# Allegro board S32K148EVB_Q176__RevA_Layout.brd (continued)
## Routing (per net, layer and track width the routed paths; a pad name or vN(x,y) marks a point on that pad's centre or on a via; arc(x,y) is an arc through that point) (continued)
P3V3_ENET: length 13.7
  TOP w0.279: J16.1 118.29,62.05 118.88,61.45 C549.1 119.49,62.04 119.21,62.04 118.71,62.55 J16.3
  TOP w0.635: R133.2 121.41,58.32 TPAD28.1 ; R133.2 C550.1 C549.1 ; R133.2 119.38,58.32 119.27,58.21 L4.2
P3V3_ENETSW: length 34.1
  TOP w0.203: U3.8 100.78,54.89 100.62,55.05 v1(99.58,55.05) ; R185.1 94.92,52.03 94.34,51.45 U10.8 ; R201.1 99.28,47.29 99.98,46.58 U12.8
  TOP w0.508: R202.1 v1(104.84,48.09) ; R201.1 98.79,48.09 98.29,47.58 v1(98.29,47.25) ; R199.1 v1(96.79,47.71) ; R144.1 TPAD31.1
  TOP w0.635: C17.1 C18.1 C19.1 101.43,58.18 101.31,58.05 R142.1 ; R142.1 R144.1 ; R142.1 100.42,57.36 v1(100.06,57.72) ; v1(97.55,50.51) 97.27,50.79 97.27,51.5 96.74,52.03 R185.1
  BOTTOM w0.203: v1(97.55,50.51) 97.78,50.28 99.15,50.28 99.38,50.51 U505.8
  BOTTOM w0.635: R521.1 99.81,60.2 R522.1 99.83,58.65 100.06,58.42 v1(100.06,57.72) ; R556.1 103.85,49.08 v1(104.84,48.09) ; R551.1 v1(104.76,51.22)
P3V3_SDA: length 59
  TOP w0.229: R301.1 14.06,12.46 R308.1
  TOP w0.279: R308.1 v1(13.04,13.37)
  TOP w0.508: v1(19.37,21.19) 19.8,20.76 U23.5 C97.1 ; v1(17.08,20.81) 17.54,21.27 R285.2 ; R281.1 v1(13.77,22.95) ; R291.1 9.6,19.57 R288.1 10.95,19.58 11.32,19.95 12.79,19.95 12.8,19.96 v1(13.64,19.96) ; R286.1 v1(25.79,20.97)
  TOP w0.635: v1(33.19,20.46) 33.74,21.02 TP55.1 34.89,21.19 TPAD48.1
  L4_PWR_1 w0.508: 21.6,27.89 J20.1 22.33,26.55
  BOTTOM w0.203: U509.1 v1(35.14,16.62)
  BOTTOM w0.279: 30.67,14.65 30.58,14.74 R622.1 ; 30.67,14.65 U511.1 ; 30.67,14.65 v1(30.63,14.65) ; U510.1 14.44,15.15 13.98,14.69 v1(13.98,14.59) 13.96,14.62 C545.1 ; v1(17.08,20.81) 16.68,20.41 16.68,20.02 16.74,19.96 U510.11 ; v1(13.64,19.96) 13.64,19.44 14.01,19.07 14.01,18.61 14.47,18.15 U510.7 ; v1(17.87,8.09) R631.1 ; U513.7 21.43,13.72 21.15,14.01 v1(21.15,14.21)
  BOTTOM w0.305: C535.1 16.03,22.26 16.52,21.77 16.52,21.38 v1(17.08,20.81) ; U514.1 16.96,12.24 16.73,12 16.73,10.48 16.95,10.26 16.95,9.11 17.49,8.57 17.49,8.46 v1(17.87,8.09) ; U512.1 26.64,15.06 26.4,15.3 25.78,15.3 v1(25.78,15.3) 25.44,15.63 R621.1
  BOTTOM w0.406: v1(13.04,13.37) C545.1 ; R605.1 21.73,26.68
  BOTTOM w0.508: R607.1 v1(13.5,26.32) ; 21.73,26.68 J20.1 ; C538.1 C536.1 13.14,20.46 v1(13.64,19.96) ; C540.1 C539.1 R613.1 32.22,16.85 32.68,16.39 R616.1 34.28,16.39 34.51,16.62 v1(35.14,16.62)
  BOTTOM w0.635: R610.1 v1(33.19,20.46) ; C533.1 R606.1 23.33,26.38 23.15,26.55 J20.1
P3V3_SW: length 308.3
  TOP w0.508: TPAD50.1 83.25,15.2 C104.1 ; v1(84.8,17.64) C99.1
  TOP w0.635: R41.1 v1(122.9,74) 123.46,74 123.91,73.55 123.91,58.4 122.22,56.72 R133.1 119.35,56.72 119.24,56.83 L4.1 118.58,56.83 TS7.1 v1(113.5,56.83) ; C85.1 34.89,31.84 TP53.1 J3.10 ; P1.1 83.53,10.75 84.54,11.77 C104.1 84.54,16.47 C99.1 ; R182.2 50.19,52.35 TP26.1 52.65,52.91 R633.2 52.65,55.4 TPAD35.1 ; R288.2 v1(8.69,21.18)
  L4_PWR_1 w0.635: v1(84.8,17.64) 85.5,17.64 85.74,17.4 105.56,17.4 106.03,17.87 106.03,43.23 106.77,43.96 106.77,47.38 113.31,53.92 113.31,54.1 113.68,54.47 113.68,56.65 v1(113.5,56.83) 111.62,56.83 106.64,61.81 101.28,61.81 98.5,64.59 98.14,64.59 v1(97.65,65.09) ; J7.1 36.78,70.66 37.34,70.66 37.74,70.25 37.74,65.21 38.38,64.58 40.37,64.58 41.01,63.94 41.01,62.85 42.18,61.68 42.18,56.78 47.56,51.39 TP26.1
  L5_PWR_2 w0.508: J3.10 36.54,29.17 ; J3.10 35.52,30.19 ; J3.10 35.52,28.15 ; J3.10 34.51,29.17
  L5_PWR_2 w0.635: J7.1 36.93,73.02 44.42,73.02 45.22,72.22 50.74,72.22 53.02,74.51 57.82,74.51 57.99,74.34 71.63,74.34 73.53,72.44 81.25,72.44 82.7,73.89 91.92,73.89 96.24,69.57 96.24,64.36 96.65,63.95 97.23,63.95 97.65,64.38 v1(97.65,65.09)
  L6_INT_2 w0.508: v1(103.42,79.66) 108.06,79.66 109.56,81.16 115.74,81.16 v1(122.9,74)
  L6_INT_2 w0.635: J7.1 34.38,73.06 30.98,73.06 30.06,72.15 20.64,72.15 19.24,73.54 17.82,73.54 17.44,73.92 13.68,73.92 12.66,74.94 7.66,74.94 v1(6.01,76.59)
  BOTTOM w0.508: R574.2 L500.2 39.46,39.3 38.98,38.82 38.98,37.98 v1(38.15,37.16) ; R501.2 v1(103.42,79.66) ; v1(97.65,65.09) 97.65,64.45 98.41,63.69 R521.2
  BOTTOM w0.635: R504.2 v1(6.01,76.59)
P5V0: length 310.9
  TOP w0.635: C113.1 C112.1 22.57,13.14 TPAD51.1 ; C113.1 23.69,10.75 v1(24.04,11.11) ; C113.1 P1.49 ; TS12.1 104.41,40.83 v1(104.05,41.18) ; v1(14.17,74.85) R12.1 R9.1 ; C79.1 TP52.1 J3.13 ; TPAD2.1 v1(122.9,75.78) ; v1(46.9,55.59) 46.9,53.68 47.21,53.38 R181.2
  TOP w0.762: J18.3 J7.3 37,68.01 37.81,68.01 J8.2 ; R35.1 R6.1 TPAD2.1 ; D6.A1 D6.A2 ; D6.A2 D6.A3 ; D6.A2 102.91,38.31 103.01,38.42 TS12.1
  L4_PWR_1 w0.635: J18.3 34.29,68.6 34.29,72.9 33.54,73.65 31.08,73.65 30.11,72.68 20.49,72.68 19.48,73.68 15.34,73.68 v1(14.17,74.85) ; v1(46.9,55.59) 45.71,55.59 44.95,56.35 44.95,65.11 43.09,66.96 41.29,66.96 J8.2 45.3,69.23 45.42,69.34 54.03,69.34 57.53,65.83 81.51,65.83 83.26,67.59 97.79,67.59 v1(99.38,66) 99.38,72.5 100.95,74.08 121.2,74.08 v1(122.9,75.78)
  L5_PWR_2 w0.635: v1(104.05,41.18) 104.05,45.53 106.64,48.12 106.64,58.15 102.45,62.34 102.45,62.93 v1(99.38,66) ; v1(24.04,11.11) 25.49,9.66 27.27,9.66 28.77,11.16 30.87,11.16 32.04,9.99 44.59,9.99 48.04,13.45 48.04,29.7 46.67,31.07 39.97,31.07 J3.13 38.06,32.43 39.98,34.35 45.6,34.35 47.28,36.03 47.28,38.57 49.14,40.42 49.14,45.86 52.79,49.52 52.79,52.08 49.29,55.59 v1(46.9,55.59)
  BOTTOM w0.635: v1(99.38,66) 99.83,65.54 R522.2
P5V0_SDA_USB_CONN_VBUS: length 8.4
  TOP w0.279: v1(8.12,10.45) 8.41,10.74 L9.1
  TOP w0.406: J24.1 5.2,11.87 6.62,10.45 v1(8.12,10.45)
  BOTTOM w0.279: v1(8.12,10.45) 8.85,10.45 9.13,10.73 9.13,11.36 8.93,11.57 U515.5
P5V0_V1SBC: length 106.2
  TOP w0.279: 27.83,58.25 27.55,58.53 v1(27.55,58.61)
  TOP w0.356: U9.6 27.57,51.45 27.88,51.14
  TOP w0.406: R140.1 27.83,58.25
  TOP w0.508: R132.1 25.74,61.1 25.77,61.12 25.77,61.16 v1(25.77,61.16) ; v1(30.31,52.39) 30.31,52.31 30.19,52.18 TS10.1
  TOP w0.635: C31.1 31.85,52.8 31.85,52.47 32.02,52.31 C45.1 C47.1 30.7,49.62 TS10.1 28.85,50.12 27.88,51.1 27.88,51.14 ; 39.03,73.06 39.03,73.62 TPAD7.1
  TOP w0.762: 39.03,73.06 J8.1
  L3_INT_1 w0.508: v1(27.55,58.61) 28,59.07 30.2,59.07 31.66,57.6 31.66,55.89 30.42,54.65 30.42,53.12 30.31,53.02 v1(30.31,52.39)
  L5_PWR_2 w0.635: v1(27.55,58.61) 25.77,60.38 v1(25.77,61.16) 26.26,61.65 26.26,63.17 20.23,69.2 17.28,69.2 TP5.1 16.29,73.59 19.72,73.59 21.45,71.87 28.82,71.87 29.97,73.02 32.89,73.02 33.67,72.25 33.67,71.99 35.17,70.5 37.76,70.5 J8.1
  BOTTOM w0.406: v1(27.55,58.61) 27.32,58.38 R531.1
  BOTTOM w0.508: R517.2 22.34,64.51 22.95,65.12 22.95,66.74 20.76,68.92 17.56,68.92 TP5.1 14.59,67.07 17.72,63.94 17.72,59.8 18.45,59.07 R526.1
P5V0_V2SBC: length 30.7
  TOP w0.279: U9.3 27.64,49.5 27.83,49.31
  TOP w0.406: 27.83,49.31 28.49,48.65 28.49,48.32 R204.1 29.63,47.61 29.98,47.25 30.49,47.25 v1(30.77,46.98)
  L5_PWR_2 w0.635: v1(30.77,46.98) 30.87,46.87 30.87,41.92 22.95,34 JP1.1
  BOTTOM w0.508: JP1.1 21.68,31.76 21.65,31.79 J15.1
  BOTTOM w0.635: C528.1 C526.1 31.18,46.57 v1(30.77,46.98)
P5V_SDA: length 13
  TOP w0.279: R293.1 7.33,16.9 v1(7.84,17.41) 8.93,17.41 9.36,16.98 9.36,16.29 9.58,16.07 U24.1
  TOP w0.406: C89.1 14.57,18.04 14.26,17.74 14.09,17.74 ; v1(14.09,17.79) 14.09,17.74 ; 14.09,17.74 14.82,17.01 C103.1
  TOP w0.508: v1(9.17,12.86) 9.81,12.23 L9.2
  TOP w0.635: C111.1 v1(9.17,12.86)
  BOTTOM w0.279: R615.1 v1(25.31,17.66) ; U510.6 14.23,17.65 v1(14.09,17.79) ; v1(14.72,9.54) 15.24,9.54 15.51,9.81 R628.1
P5V_SDA_PSW: length 86.2
  TOP w0.508: TPAD49.1 12.9,17.51 U24.6
  TOP w0.635: TPAD49.1 12.38,17.51 11.95,17.08 v1(10.4,17.08)
  L5_PWR_2 w0.635: v1(7.05,29.47) 7.05,50.3 7.67,50.92 7.67,55.42 8.65,56.4 14.01,56.4 16.34,54.06 19.75,54.06 22.67,56.98 24.45,56.98 25.41,56.02 26.63,56.02 28.89,58.28 28.89,61.37 28.4,61.86 28.4,62.84 30.24,64.68 37.02,64.68 J8.3
  BOTTOM w0.635: v1(10.4,17.08) 7.05,20.43 v1(7.05,29.47)
VBAT: length 56.8
  TOP w0.635: J3.22 C86.1 ; TP2.1 J18.1 ; 16.32,65.39 C12.1 ; C12.1 16.83,65.9 ; C12.1 15.81,65.9 ; J3.1 C82.1
  TOP w0.889: R180.2 9.08,51.32 9.91,52.14 v1(10.25,52.14) R163.1 ; R180.2 v1(6.97,51.32) ; R180.2 v1(8.22,50.44) ; D4.A 17.6,63.08 ; D4.A 18.49,64.32 ; D4.A 16.71,64.32 ; D4.A 17.6,65.57 ; J9.1 12.29,63.97 ; J9.1 8.46,63.97 ; J9.1 10.38,64.88
  TOP w1.016: J3.3 J3.6
  L4_PWR_1 w0.508: 26.89,29.17 J3.1 ; J3.1 27.9,28.15 ; J3.1 28.92,29.17 ; J3.1 27.9,30.19 ; 26.89,24.09 J3.3 ; J3.3 28.92,24.09 ; J3.3 27.9,25.11 ; J3.6 31.46,24.09 ; J3.6 30.44,25.11 ; J3.6 29.43,24.09 ; 8.46,63.97 J9.1 ; J9.1 10.38,63.05 ; J9.1 10.38,64.88 ; J9.1 12.29,63.97 ; 2.63,28.15 J17.2 ; J17.2 3.64,29.17 ; J17.2 3.64,27.14 ; J17.2 4.66,28.15 ; J3.22 45.68,30.19 ; J3.22 45.68,28.15 ; J3.22 44.67,29.17 ; J18.1 33.33,71.77 ; J18.1 31.42,71.77 ; J18.1 32.37,70.81 ; J18.1 32.37,72.72 ; 3.64,41.23 J13.2 ; J13.2 4.66,42.25 ; J13.2 3.64,43.27 ; J13.2 2.63,42.25
  vias: v1(19.01,66.23) v1(19.01,65.54)
VCC_HYPRFLASH: length 23.9
  L6_INT_2 w0.191: v1(34.79,41.59) 34.28,41.59 33.94,41.93 v1(32.83,43.04)
  BOTTOM w0.279: R574.1 R575.1
  BOTTOM w0.406: v1(34.79,41.59) 35.52,41.59 35.93,42 TPAD504.1 37.13,41.98 R575.1 ; v1(32.83,43.04) 31.41,43.04 29.12,40.75 26.37,40.75 25.12,42 C529.1 C531.1 C532.1 U508.8 ; L500.1 R574.1
VCCA_LS_SBC: length 90.1
  TOP w0.508: R153.1 34.89,55.63 35.15,55.89 35.83,55.89 v1(36.23,56.29)
  L3_INT_1 w0.635: v1(30.31,47.92) 30.8,48.41 30.81,48.41 v1(35.24,52.84) ; v1(23.28,63.97) 21.24,63.97 19.72,62.44 v1(18.96,62.44) 17.98,62.44 13.7,58.16 v1(13.7,57.47)
  L6_INT_2 w0.635: v1(30.31,47.92) 29.81,47.42 23.76,47.42 22.8,48.39 22.8,50.58 23.66,51.45 v1(23.66,52.66) 21.81,54.52 15.79,54.52 13.7,56.6 v1(13.7,57.47) ; v1(29.93,58.43) 29.11,57.6 29.11,55.7 31.97,52.84 v1(35.24,52.84)
  BOTTOM w0.203: U507.1 27.71,49.07 28.87,47.92 v1(30.31,47.92) ; v1(13.7,57.47) 13.7,58.1 14.47,58.86 U502.1 ; v1(36.23,56.29) 36.23,56.91 35.37,57.77 U503.1 ; U500.1 v1(23.28,63.97) ; 22.87,54.72 22.29,54.72 22.14,54.87 U504.1 ; U506.1 35.07,52.13 35.24,52.31 v1(35.24,52.84) ; v1(29.93,58.43) 29.93,58.91 30.1,59.08 30.1,59.39 29.83,59.65 U501.1
  BOTTOM w0.406: v1(35.24,52.84) 35.24,53.43 35.22,53.45 35.22,54.09 36.23,55.1 v1(36.23,56.29)
  BOTTOM w0.508: 26.61,53.88 C521.1 TP505.1 ; v1(23.66,52.66) 24.3,52.66 24.35,52.72 TP505.1 ; C520.1 22.97,54.62 22.87,54.72 ; TP505.1 26.61,52.06 26.1,51.55 R550.2 ; v1(18.96,62.44) 21.57,59.84 21.57,59.33 R525.2
  BOTTOM w0.635: v1(23.66,52.66) 23.66,53.27 C522.1 C520.1 ; C519.1 26.61,53.88
VCCA_VTRANSL: length 117.6
  TOP w0.279: C80.1 50.89,33.82 51.03,33.96 U16.14 ; C46.1 35.32,49.41 35.51,49.22 35.51,49.2 v1(35.88,48.83) 36.6,48.83 36.84,49.07 U11.14 ; C68.1 37.38,39.33 37.39,39.32 U14.14 ; U22.14 62.58,32.81 62.57,32.8 C83.1 ; U13.14 46.77,43.19 47.03,42.94 v1(47.56,42.94)
  TOP w0.406: C61.1 47.89,43.27 v1(47.56,42.94)
  TOP w0.508: C68.1 35.45,39.33 v1(35.14,39.63) ; C80.1 48.65,33.11 v1(47.38,34.38) 47.38,32.42 49.06,30.74 49.06,28.27 49.43,27.9 58.89,27.9 59.66,28.67 59.66,29.69 60.41,30.44 62.09,30.44 v1(62.57,30.92) C83.1
  TOP w0.635: TS8.1 40.65,52.54 39.76,53.43 R176.1 v1(39.2,54.7) ; C59.1 C61.1 TPAD40.1 48.6,41.49 L7.2 R242.2
  L3_INT_1 w0.508: v1(62.57,30.92) 63.28,31.63 v1(63.28,33.54) ; v1(35.88,48.83) 35.88,47.89 35.57,47.58 35.57,45.59 36.9,44.26 36.93,44.26 37.45,43.73 37.45,42.78 35.14,40.46 v1(35.14,39.63)
  BOTTOM w0.406: v1(47.38,34.38) 47.74,34.02 49.49,34.02 50.46,34.99 50.46,38.82 48.65,40.63 C530.1 48.65,42.66 48.37,42.94 v1(47.56,42.94) 47.56,43.52 47.31,43.77 C527.1
  BOTTOM w0.508: R548.1 R547.1 R546.1 38.19,54.24 38.65,54.7 v1(39.2,54.7) 39.2,53.81 39.56,53.45 39.56,51.17 37.22,48.83 v1(35.88,48.83) 35.88,45.58 R572.1 R571.1 R570.1 40.75,43.14 42.66,41.23 R573.1 42.66,40.4 43.19,39.86 R579.1 R578.1 R577.1 R576.1 47.08,39.43 R582.1 R584.1 R588.1 R593.1 47.08,34.68 v1(47.38,34.38)
  BOTTOM w0.635: v1(63.28,33.54) R603.1 R597.1 R594.1 R589.1
VCCB_VTRANSL: length 129.3
  TOP w0.279: U14.1 37.39,37.82 37.38,37.81 C75.1 ; C55.1 35.85,47.99 36.54,47.31 v1(36.84,47.31) U11.1 ; C84.1 64.1,32.8 64.08,32.81 U22.1 ; C81.1 52.41,33.82 52.53,33.93 U16.1 ; R214.1 v1(42.3,44.28) ; C56.1 48.12,46.31 47.79,45.98 47.79,45.6 47.47,45.29 U13.1
  TOP w0.406: C75.1 35.65,37.81 v1(35.27,38.19) ; v1(48.98,48.91) 48.98,49.49 48.58,49.9 R182.1 R181.1 46.15,50.75 45.81,51.09 C41.1 C32.1
  TOP w0.508: R273.1 68.54,32.75 66.46,30.66 64.46,30.66 64.1,31.02 C84.1
  TOP w0.635: C81.1 53.1,33.11 53.61,33.61 TPAD45.1 55.07,32.87 v1(55.07,32.87) ; C32.1 v1(44.34,51.14) ; R252.1 R258.1 R263.1 R273.1 v1(70,33.74) TS14.1 ; C56.1 C53.1 v1(48.98,48.91)
  L3_INT_1 w0.508: v1(42.3,44.28) 44.01,45.98 44.01,48.75 43.75,49.01 43.75,50.58 44.31,51.14 v1(44.34,51.14) ; v1(43.24,32.56) 42.6,31.92 38.22,31.92 36.23,33.91 36.23,37.22 v1(35.27,38.19) 37.02,39.94 37.02,41.45 38.09,42.51 38.09,44 37.19,44.89 37.16,44.89 36.21,45.85 36.21,46.67 v1(36.84,47.31)
  L6_INT_2 w0.508: v1(55.07,32.87) 51.03,32.87 50.63,32.47 46.44,32.47 46.36,32.56 v1(43.24,32.56)
  BOTTOM w0.406: v1(44.34,51.14) 44.31,51.14 43.88,50.71 R553.2 43.37,50.66 R559.1 ; v1(43.24,32.56) R599.1
  BOTTOM w0.508: v1(55.07,32.87) 56.28,31.66 60.77,31.66 61.18,32.07 66.23,32.07 67.91,33.74 v1(70,33.74) ; v1(36.84,47.31) 37.34,47.8 38.48,47.8 38.98,47.31 R566.1 40.2,47.03 42.3,44.92 v1(42.3,44.28) R568.1 R569.1
  BOTTOM w0.635: R599.1 42.15,33.31 42.1,33.36 41.26,33.36 R600.1 R601.1 R602.1 ; R557.1 R558.1 R559.1 R560.1 ; R587.1 R592.1 R596.1 56.6,34.02 55.95,33.36 55.56,33.36 v1(55.07,32.87) 54.25,32.87 R598.1
VDD: length 188.9
  TOP w0.635: TPAD12.1 59.78,70.06 R59.1 ; TS15.1 40.22,14.54 39.67,13.99 v1(38.28,13.99) R299.2 ; R59.1 R60.1 ; R59.1 57.84,71.3 J19.2
  L4_PWR_1 w0.635: J19.2 56,71.17 52.35,71.17 51.47,72.04 47.84,72.04 46.55,73.34 37.3,73.34 35.98,74.66 30.62,74.66 29.83,73.87 28.13,73.87 26.52,75.49 18.67,75.49 16.57,77.58 13.74,77.58 13.11,76.94 13.11,75.66 v1(13.22,75.55)
  L5_PWR_2 w0.635: v1(38.28,13.99) 35.15,13.99 29.5,19.64 21.25,19.64 20.64,19.04 16.24,19.04 14.57,20.71 11.11,20.71 9.89,19.49 4.99,19.49 2.3,22.18 2.3,59.07 2.93,59.7 4.74,59.7 6.85,61.81 6.85,72.65 9.74,75.55 v1(13.22,75.55) ; J7.2 36.96,67.94 40.31,67.94 40.59,67.66 54.2,67.66 J19.2
  BOTTOM w0.635: v1(13.22,75.55) 13.22,75.47 13.14,75.47 12.84,75.17 TPAD502.1 R505.2
VDD_MCU: length 71.4
  TOP w0.203: U8.39 60.29,67.4 60.29,67.4 60.29,67.78 60.29,67.79 v1(60.29,68.04) ; v1(59.93,47.43) 59.2,47.43 59.2,47.42 58.82,47.42 58.81,47.43 U7.67 ; U8.77 v1(54.18,48.43) ; U7.11 72.29,63.42 72.28,63.41 72.28,63.01 72.28,63 72.28,62.78 v1(72.29,62.77) ; U8.59 v1(54.17,57.43) ; 83.93,52.03 83.72,52.03 83.22,52.52 82.48,52.52 82.44,52.48 ; 77.8,40.98 v1(77.8,39.32) ; U7.51 58.81,55.43 58.81,55.44 59.2,55.44 59.2,55.43 v1(59.92,55.43) ; 68.29,40.98 v1(68.29,39.32)
  TOP w0.254: U7.91 v1(68.79,44.12) ; U8.152 82.2,52.43 82.22,52.48 82.44,52.48 ; U7.124 77.64,52.43 v1(77.11,52.96) ; U8.18 v1(70.79,67.57) ; U8.172 v1(82.44,62.44) ; U7.32 v1(61.79,63.24)
  TOP w0.279: U7.124 81.24,52.43 U8.152
  TOP w0.508: C9.1 60.29,68.94 v1(60.29,68.04) ; C50.1 53.97,48.22 v1(54.18,48.43) ; v1(54.17,57.43) 53.78,57.43 53.58,57.24 C23.1 ; C72.1 77.8,38.45 v1(77.8,39.32) ; C73.1 68.54,39.07 v1(68.29,39.32) ; C44.1 83.93,52.03
  TOP w0.635: R59.2 58.1,72.9 58.06,72.86 J19.1 ; TPAD44.1 77.89,38.26 C72.1 ; D2.1 83.27,68.29 82.87,67.88 v1(81.29,67.88) ; D2.1 82.19,69.43 82.07,69.3 L1.1 ; D2.1 84.35,69.43 84.94,70.01 84.94,70.95 85.57,71.59 TS4.1 ; TPAD32.1 C23.1
  L5_PWR_2 w0.508: 55.9,72.86 J19.1 ; J19.1 56.86,73.81 ; J19.1 56.86,71.9 ; J19.1 57.81,72.86
  BOTTOM w0.203: C503.1 83.27,62.62 83.11,62.46 82.94,62.46 82.92,62.44 v1(82.44,62.44) ; 71.03,68.77 70.79,68.53 v1(70.79,67.57) ; v1(61.79,63.24) 61.79,62.76 61.81,62.74 61.81,62.57 61.81,62.57 C505.1 ; v1(72.29,62.77) 72.78,62.28 73.02,62.28 73.49,61.81 C510.1
  BOTTOM w0.508: v1(68.79,44.12) 68.66,44.26 68.66,44.86 68.8,45 C525.1 ; C518.1 60.08,55.33 59.98,55.43 v1(59.92,55.43) ; C504.1 74.76,61.81 C510.1 ; v1(77.11,52.96) 76.9,52.74 C524.1 ; C502.1 71.03,69.28 71.03,68.77
  BOTTOM w0.635: C516.1 60.67,56.25 60.79,56.12 C518.1 ; v1(81.29,67.88) 81.29,68.72 80.71,69.3 R509.2
VDD_MCU_ENETSW: length 35.4
  TOP w0.203: R178.1 93.18,51.67 93.69,51.17 U10.1 ; U12.1 99.31,45.93 99.19,46.06 R207.1 ; U3.1 99.44,53.81 99.19,53.55 L6.2
  TOP w0.508: v1(93.97,46.11) 92.62,47.46 R200.1 ; R207.1 97.57,46.06 v1(97.19,46.44) ; R188.1 v1(104.66,50.38) ; R190.1 98.22,49.87 97.89,49.54 97.68,49.54 v1(97.57,49.44) ; R156.1 v1(105.74,53.81) ; R217.1 v1(105.37,44.52)
  TOP w0.635: R179.2 L6.2 98.64,54.7 C28.1 C27.1 95.72,54.95 TPAD36.1 93.81,54.19 v1(93.18,53.55) R178.1
  BOTTOM w0.203: v1(98.13,51.19) 98.13,52.11 98.39,52.36 U505.1
  BOTTOM w0.508: v1(104.72,55.11) 103.56,56.27 R539.1 ; v1(94.17,55.29) 94.68,54.78 95.4,54.78 95.57,54.95 C27.1 95.92,54.14 R545.1
VDD_MCU_PERH: length 159.4
  TOP w0.406: 87.46,67.65 85.38,67.65 85.26,67.52 TPAD17.1 ; R121.1 R113.1
  TOP w0.508: TP6.1 v1(97.07,70.06) 96.94,69.94 R72.1 ; J5.10 C88.1 ; R36.1 21.04,74.31 v1(21.58,73.77) ; R107.1 R95.1 R90.1 v1(97.27,66.89) ; J6.14 82.51,78.7 82.51,76.03 C2.1 84.04,73.95 84.59,73.39 v1(84.59,72.98) ; R37.1 v1(24.09,73.89) ; v1(95.03,52.94) 95.64,53.55 L6.1 ; v1(83.67,62) 84.16,61.5 R113.1 ; R60.2 v1(63.12,72.9) ; R242.1 49.62,38.8 49.77,38.64 49.77,38.64 v1(49.81,38.64) ; R161.2 v1(114.01,53.81)
  TOP w0.635: SW4.3 SW4.1 v1(97.16,11.38) ; SW3.3 SW3.1 90.59,9.81 v1(90.59,11.59) 89.8,12.38 TS16.1 ; R179.1 L6.1 ; C88.1 83.78,23.51 v1(83.32,23.05) ; L7.1 R242.1 ; J3.4 30.54,29.27 C87.1 ; C551.1 84.54,66.99 TPAD17.1 84.54,68.35 85.7,69.51 85.7,70.13 v1(86.19,70.62)
  L3_INT_1 w0.762: v1(24.09,73.89) 24.63,73.35 24.69,73.35 28.59,69.45 28.59,68.29 32.47,64.4 42.04,64.4 42.45,64.81 43.08,64.81 43.14,64.74 v1(43.71,64.74)
  L4_PWR_1 w0.508: v1(21.58,73.77) 22.16,74.36 23.3,74.36 23.33,74.34 23.64,74.34 v1(24.09,73.89) ; 83.78,25.6 J5.10 ; J5.10 83.78,27.66 ; J5.10 82.75,26.63 ; J5.10 84.81,26.63
  L5_PWR_2 w0.762: J3.4 28.92,30.69 25.46,30.69 24.73,29.96 22.03,29.96 21.42,30.57 21.42,32.01 19.77,33.67 19.77,36.48 23.23,39.94 23.23,47.08 v1(22.06,48.25) 22.06,49.27 25.94,53.15 32.41,53.15 32.85,53.59 32.85,53.99 34.38,55.51 34.38,59.6 39.52,64.74 v1(43.71,64.74)
  BOTTOM w0.508: R518.1 96.15,60.74 v1(97.14,59.75) ; R550.1 23.94,51.55 22.06,49.67 v1(22.06,48.25)
VDDA_MCU: length 33.5
  TOP w0.16: U7.13 v1(71.29,62.62) ; v1(69.78,67.63) 69.79,67.63 U8.20
  TOP w0.203: 69.78,68.7 69.78,68.44 69.79,68.43 69.79,68.12 69.78,68.11 v1(69.78,67.63)
  TOP w0.508: L1.2 79.26,69.3 v1(78.36,70.2) 77.7,70.2 TPAD14.1 76.03,69.3 75.91,69.43 D1.1 C5.1 72.86,69.3 C7.1 C6.1 69.78,68.76 69.78,68.7
  TOP w0.635: L1.2 80.1,70.71 79.44,71.37 TS3.1
  BOTTOM w0.191: 71.29,63.81 71.29,63.45 71.3,63.43 71.3,63.11 71.29,63.1 v1(71.29,62.62)
  BOTTOM w0.203: 70.07,68.79 69.78,68.51 69.78,68.44 69.79,68.43 69.79,68.12 69.78,68.11 v1(69.78,67.63)
  BOTTOM w0.381: 70,66.67 69.78,66.9 v1(69.78,67.63)
  BOTTOM w0.508: 70,66.67 71.29,65.38 71.29,63.81 ; R509.1 v1(78.36,70.2) ; C506.1 70.83,62.16 v1(71.29,62.62) ; 70.07,68.79 70.07,69.14 70.09,69.16 R508.2
  BOTTOM w0.635: C509.1 C508.1 C507.1 C506.1 C511.1
ADC_POT: length 83
  TOP w0.406: v1(110.48,49.36) C48.1 R194.2 TP27.1
  L3_INT_1 w0.191: v1(93.99,52.03) 93.99,47.62 94.46,47.16 94.68,47.16 96.38,45.46 106.57,45.46 v1(110.48,49.36)
  L6_INT_2 w0.191: v1(93.99,52.03) 92.37,52.03 90.82,50.48 90.82,48.6 89.52,47.31 89.52,43.77 85.24,39.48 84.09,39.48 84.08,39.49 83.93,39.49 ; v1(65.26,38.11) 69.05,38.11 70.85,36.31 73.98,36.31 75.93,38.26 81.93,38.26 82.28,38.62
  L6_INT_2 w0.203: 82.28,38.62 83.15,39.48 83.2,39.48 83.21,39.49 83.93,39.49
  BOTTOM w0.203: 67.27,38.62 67.81,39.15 67.81,39.56 68.08,39.84 68.08,44.94 67.5,45.53 67.5,46.47 68.77,47.74 69.62,47.74 70.27,47.09 R634.1
  BOTTOM w0.406: 67.27,38.62 66.77,38.11 v1(65.26,38.11) 64.68,38.11 64.45,38.34 R583.1
CAN_H: length 18.8
  TOP w0.254: J11.1 4.6,57.43 6.64,57.43 6.93,57.72 C20.1 7.87,57.72 8.17,57.43 8.82,57.43 8.89,57.5 9.46,57.5 9.77,57.56 9.97,57.86 R125.1 11.65,58.38 12.08,57.94 12.57,57.94 12.9,58.27 12.9,58.31 12.94,58.35 ; 13.65,59.07 13.65,61.17 14.34,61.86 TP11.1
  TOP w0.279: 13.65,59.07 12.94,58.35
  TOP w0.406: R112.2 TP11.1
CAN_L: length 14.4
  TOP w0.254: 13.25,58.05 13.2,58 13.17,58 12.72,57.56 12.55,57.56 12.31,57.31 12.31,57.26 12.28,57.24 R138.2 TP20.1 10.15,56.99 9.85,57.19 9.49,57.12 9.05,57.12 8.98,57.05 8.17,57.05 7.87,56.75 C25.1 6.93,56.75 6.64,57.05 4.85,57.05 J11.2
  TOP w0.279: R135.2 14.03,58.84 13.25,58.05
CANH_OUT: length 74.6
  TOP w0.254: R119.2 15.91,60.84 15.44,60.37 15.29,60.37 14.82,60.84 v1(14.47,60.84)
  L6_INT_2 w0.191: v1(14.47,60.84) 13.99,60.58 13.69,60.67 12.32,60.67 11.4,59.76 11.4,54.88 11.4,54.62 16.37,49.65 16.8,49.65 17.45,49 17.45,42.86 27.81,32.49 27.81,31.15 29.01,29.95 29.01,22.64 29.56,22.08 v1(29.56,21.68)
  BOTTOM w0.254: v1(29.56,21.68) 29.56,22.08 29.12,22.51 27.98,22.51 27.65,22.18 27.65,21.37 28.28,20.74 29.76,20.74 30.92,21.91 33.82,21.91 34.28,22.36 41.52,22.36 41.9,21.98 43.68,21.98 44.22,22.53 44.22,23.01 J3.21
CANL_OUT: length 75.6
  TOP w0.254: v1(14.16,59.8) 14.65,60.29 14.83,60.29 15.28,59.85 R134.2
  L6_INT_2 w0.191: v1(30.19,22.31) 29.78,22.31 29.32,22.77 29.32,30.08 28.13,31.28 28.13,32.62 17.77,42.99 17.77,49.13 16.93,49.97 16.5,49.97 11.72,54.75 11.72,59.62 12.45,60.35 13.64,60.35 13.9,60.28 v1(14.16,59.8)
  BOTTOM w0.254: J3.24 44.6,23.01 44.6,22.37 43.83,21.6 41.74,21.6 41.36,21.98 34.44,21.98 33.98,21.52 31.08,21.52 29.91,20.36 28.12,20.36 27.27,21.21 27.27,22.34 27.82,22.9 29.28,22.9 29.87,22.31 v1(30.19,22.31)
ENET_MII_TXC: length 8.9
  TOP w0.279: J16.20 108.87,66.55 107.68,65.36 v1(106.64,65.36) R96.1
  BOTTOM w0.203: R513.1 R96.1 v1(106.64,65.36)
ENETSW_INH: length 104.5
  TOP w0.406: R2.2 v1(102.45,78.7)
  L3_INT_1 w0.191: v1(102.45,78.7) 103.52,78.7 104.1,78.12 104.1,70.22 103.91,70.03 102.99,70.03 101.85,68.9 101.85,66.99 101.21,66.35 101.21,60.37 98.69,57.85 98.69,54.31 98.78,54.22 100.09,54.22 100.18,54.31 100.18,56.05 100.28,56.14 100.41,56.14 100.5,56.05 100.5,54.31 100.59,54.22 100.72,54.22 100.82,54.31 100.82,56.05 100.91,56.14 101.04,56.14 101.13,56.05 101.13,54.31 101.23,54.22 101.36,54.22 101.45,54.31 101.45,56.05 101.55,56.14 101.68,56.14 101.77,56.05 101.77,54.31 101.86,54.22 101.99,54.22 102.09,54.31 102.09,56.05 102.18,56.14 102.31,56.14 102.4,56.05 102.4,54.31 102.5,54.22 102.82,54.22 102.91,54.12 102.91,53.99 102.82,53.9 98.78,53.9 98.69,53.81 98.69,53.67 98.78,53.58 102.82,53.58 102.91,53.49 102.91,53.36 102.82,53.26 98.78,53.26 98.69,53.17 98.69,53.04 98.78,52.95 102.82,52.95 102.91,52.85 102.91,52.72 102.82,52.63 98.78,52.63 98.69,52.54 98.69,52.4 98.78,52.31 102.82,52.31 102.91,52.22 102.91,52.09 102.82,51.99 98.78,51.99 98.69,51.9 98.69,51.77 98.78,51.68 102.82,51.68 102.91,51.58 102.91,51.45 102.82,51.36 101.52,51.36 101.43,51.27 101.43,50.71 101.33,50.61 101.2,50.61 101.11,50.71 101.11,51.27 101.02,51.36 100.88,51.36 100.79,51.27 100.79,50.71 100.7,50.61 100.57,50.61 100.47,50.71 100.47,51.27 100.38,51.36 100.25,51.36 100.16,51.27 100.16,50.71 100.06,50.61 99.93,50.61 99.84,50.71 99.84,51.27 99.75,51.36 99.61,51.36 99.52,51.27 99.52,50.71 99.43,50.61 99.3,50.61 99.2,50.71 99.2,51.27 99.11,51.36 98.78,51.36 98.69,51.27 98.69,50.77 98.13,50.21 98.13,49.84 98.23,49.75 99.42,49.75 99.51,49.66 99.51,49.52 99.42,49.43 98.23,49.43 98.13,49.34 v1(98.13,48.37)
  BOTTOM w0.203: v1(98.13,48.37) 98.13,48.6 TPAD503.1 R556.2 99.76,50.23 99.78,50.25 U505.7
ENETSW_RESET: length 105.3
  TOP w0.279: U22.4 66.28,35.52 v1(66.54,35.77) R258.2
  TOP w0.406: R1.2 v1(104.48,80.46)
  L3_INT_1 w0.191: v1(99.17,57.62) 101.84,60.28 101.84,64.67 102.17,65 102.17,68.36 102.83,69.02 103.87,69.02 104.48,69.63 104.48,76.1 104.58,76.19 107.13,76.19 107.23,76.28 107.23,76.41 107.13,76.51 104.58,76.51 104.48,76.6 104.48,76.73 104.58,76.82 107.13,76.82 107.23,76.92 107.23,77.05 107.13,77.14 104.58,77.14 104.48,77.23 104.48,77.37 104.58,77.46 107.13,77.46 107.23,77.55 107.23,77.68 107.13,77.78 104.58,77.78 104.48,77.87 104.48,78 104.58,78.09 107.13,78.09 107.23,78.19 107.23,78.32 107.13,78.41 104.58,78.41 104.48,78.5 104.48,78.64 104.58,78.73 107.13,78.73 107.23,78.82 107.23,78.95 107.13,79.05 104.58,79.05 104.48,79.14 104.48,79.27 104.58,79.36 107.13,79.36 107.23,79.46 107.23,79.59 107.13,79.68 104.58,79.68 104.48,79.77 v1(104.48,80.46)
  L6_INT_2 w0.191: v1(66.54,35.77) 68.77,35.77 68.87,35.68 74.25,35.68 76.2,37.63 82.41,37.63 83.57,38.78 85.44,38.78 90.16,43.51 90.16,47.04 91.45,48.34 91.45,48.35 99.17,56.08 v1(99.17,57.62)
ENETSW_RESET_A: length 5.2
  TOP w0.229: U22.11 60.72,35.52 60.66,35.58 60.51,35.58 v1(60.16,35.93)
  TOP w0.406: R251.2 R261.2 59.75,35.42 60.16,35.82 v1(60.16,35.93)
  BOTTOM w0.406: R594.2 60.62,35.42 60.16,35.88 v1(60.16,35.93)
ENETSW_SCL: length 104.5
  TOP w0.203: U10.6 94.34,49.39 94.5,49.24 R199.2
  TOP w0.406: R7.2 TPAD3.1 103.21,76.51 102.55,75.85 102.48,75.85 v1(102.32,75.7) ; R199.2 96.33,49.24 v1(96.81,48.75)
  L3_INT_1 w0.191: v1(96.81,48.75) 97.83,47.74 98.95,47.74 99.13,47.55 99.13,47.48 99.22,47.39 100.15,47.39 100.24,47.29 100.24,47.16 100.15,47.07 99.22,47.07 99.13,46.98 99.13,46.73 99,46.59 97.98,46.59 97.65,46.92 96.08,46.92 95.63,47.37 95.63,47.5 96.16,48.03 96.16,48.16 96.07,48.25 95.94,48.25 95.41,47.72 95.28,47.72 95.18,47.82 95.18,47.95 95.71,48.48 95.71,48.61 95.62,48.7 95.49,48.7 94.96,48.17 94.83,48.17 94.55,48.45 94.55,49.05 94.64,49.14 96.24,49.14 96.33,49.24 96.33,49.37 96.24,49.46 94.64,49.46 94.55,49.55 94.55,49.68 94.64,49.78 96.24,49.78 96.33,49.87 96.33,50 96.24,50.1 94.64,50.1 94.55,50.19 94.55,50.51 94.64,50.6 96.24,50.6 96.33,50.69 96.33,50.82 96.24,50.92 94.64,50.92 94.55,51.01 94.55,51.14 94.64,51.23 96.24,51.23 96.33,51.33 96.33,51.46 96.24,51.55 94.64,51.55 94.55,51.64 94.55,51.78 94.64,51.87 95.42,51.87 95.51,51.96 95.51,52.23 95.6,52.32 95.73,52.32 95.83,52.23 95.83,51.96 95.92,51.87 96.24,51.87 96.56,52.19 96.56,52.55 96.47,52.64 95.6,52.64 95.51,52.73 95.51,52.87 95.6,52.96 96.47,52.96 96.56,53.05 96.56,53.18 96.47,53.28 95.6,53.28 95.51,53.37 95.51,53.5 95.6,53.59 96.47,53.59 96.56,53.69 96.56,54 96.47,54.1 95.91,54.1 95.82,54.19 95.82,54.32 95.91,54.41 96.47,54.41 96.56,54.51 96.56,55.93 96.81,56.18 96.94,56.18 97.37,55.75 97.51,55.75 97.6,55.84 97.6,55.97 97.17,56.41 97.17,56.54 97.88,57.25 97.88,57.58 97.79,57.67 97.13,57.67 97.03,57.76 97.03,57.9 97.13,57.99 97.79,57.99 97.88,58.08 97.88,59.29 98.1,59.52 98.24,59.52 98.78,58.97 98.92,58.97 99.01,59.06 99.01,59.19 98.46,59.74 98.46,59.88 98.55,59.97 98.68,59.97 99.23,59.42 99.37,59.42 99.46,59.51 99.46,59.64 98.91,60.19 98.91,60.32 99,60.42 99.13,60.42 99.68,59.87 99.81,59.87 99.91,59.96 99.91,60.09 99.08,60.92 99.08,64.89 99.86,65.67 99.86,66.78 99.77,66.87 99.17,66.87 99.08,66.96 99.08,67.09 99.17,67.19 100,67.19 100.09,67.28 100.09,67.41 100,67.51 99.17,67.51 99.08,67.6 99.08,67.73 99.17,67.82 100,67.82 100.09,67.92 100.09,68.05 100,68.14 99.17,68.14 99.08,68.23 99.08,68.36 99.17,68.46 100,68.46 100.09,68.55 100.09,68.68 100,68.78 99.17,68.78 99.08,68.87 99.08,69 99.17,69.09 100,69.09 100.09,69.19 100.09,69.32 100,69.41 99.17,69.41 99.08,69.5 99.08,69.63 99.17,69.73 100,69.73 100.09,69.82 100.09,69.95 100,70.05 99.17,70.05 99.08,70.14 99.08,70.27 99.17,70.36 100,70.36 100.09,70.46 100.09,70.59 100,70.68 99.17,70.68 99.08,70.77 99.08,70.9 99.17,71 100,71 100.09,71.09 100.09,71.22 100,71.32 99.17,71.32 99.08,71.41 99.08,71.54 99.17,71.63 100,71.63 100.09,71.73 100.09,71.86 100,71.95 99.17,71.95 99.08,72.04 99.08,72.17 99.17,72.27 100,72.27 100.09,72.36 100.09,72.49 100,72.59 99.17,72.59 99.08,72.68 99.08,72.81 99.17,72.9 100,72.9 100.09,73 100.09,73.47 100.66,74.04 100.66,74.17 99.75,75.08 99.75,75.21 99.84,75.3 99.97,75.3 100.88,74.39 101.01,74.39 101.11,74.49 101.11,74.62 100.2,75.53 100.2,75.66 100.29,75.75 100.42,75.75 101.33,74.84 101.46,74.84 101.56,74.94 101.56,75.07 100.65,75.98 100.65,76.11 100.74,76.2 100.87,76.2 101.78,75.29 101.91,75.29 v1(102.32,75.7)
ENETSW_SDA: length 104.2
  TOP w0.203: R185.2 95.34,50.12 U10.7
  TOP w0.406: v1(102.35,74.99) 102.81,74.99 TPAD5.1 103.47,75.65 R8.2 ; v1(96.84,49.67) 96.84,50.1 96.43,50.51 R185.2
  L3_INT_1 w0.191: v1(102.35,74.99) 102.81,75.45 102.81,77.09 102.71,77.19 101.91,77.19 101.82,77.28 101.82,77.41 101.91,77.5 102.71,77.5 102.81,77.6 102.81,78.06 103.12,78.38 103.39,78.38 103.78,77.98 103.78,77.2 103.69,77.1 103.22,77.1 103.12,77.01 103.12,76.88 103.22,76.79 103.69,76.79 103.78,76.69 103.78,76.56 103.69,76.47 103.22,76.47 103.12,76.38 103.12,76.24 103.22,76.15 103.69,76.15 103.78,76.06 103.78,75.93 103.69,75.83 103.22,75.83 103.12,75.74 103.12,75.61 103.22,75.52 103.69,75.52 103.78,75.42 103.78,75.29 103.69,75.2 103.22,75.2 103.12,75.11 103.12,74.97 103.22,74.88 103.69,74.88 103.78,74.79 103.78,74.66 103.69,74.56 103.22,74.56 103.12,74.47 103.12,74.34 103.22,74.25 103.69,74.25 103.78,74.15 103.78,73.84 103.67,73.72 102.51,73.72 102.13,73.33 102.13,72.73 101.94,72.54 101.62,72.54 101.53,72.64 101.53,73.93 101.43,74.03 101.3,74.03 101.21,73.93 101.21,72.64 101.12,72.54 100.5,72.54 100.41,72.45 100.41,72.32 100.5,72.23 102.94,72.23 103.04,72.13 103.04,72 102.94,71.91 100.5,71.91 100.41,71.82 100.41,71.68 100.5,71.59 102.94,71.59 103.04,71.5 103.04,71.37 102.94,71.27 100.5,71.27 100.41,71.18 100.41,71.05 100.5,70.96 100.97,70.96 101.06,70.86 101.06,70.16 101.15,70.06 101.28,70.06 101.38,70.16 101.38,70.86 101.47,70.96 101.6,70.96 101.69,70.86 101.69,70.16 101.79,70.06 101.92,70.06 102.01,70.16 102.01,70.86 102.1,70.96 102.94,70.96 103.04,70.86 103.04,70.55 101.49,69 101.49,68.7 101.39,68.6 100.5,68.6 100.41,68.51 100.41,68.38 100.5,68.28 101.39,68.28 101.49,68.19 101.49,68.06 101.39,67.97 100.5,67.97 100.41,67.87 100.41,67.74 100.5,67.65 101.39,67.65 101.49,67.56 101.49,67.07 100.9,66.48 100.9,65.97 100.8,65.88 100.27,65.88 100.18,65.78 100.18,65.65 100.27,65.56 100.8,65.56 100.9,65.46 100.9,65.33 100.8,65.24 100.27,65.24 100.18,65.15 100.18,65.02 100.27,64.92 100.8,64.92 100.9,64.83 100.9,64.51 100.8,64.42 99.71,64.42 99.62,64.33 99.62,64.19 99.71,64.1 100.8,64.1 100.9,64.01 100.9,63.88 100.8,63.78 99.71,63.78 99.62,63.69 99.62,63.56 99.71,63.47 100.8,63.47 100.9,63.37 100.9,63.24 100.8,63.15 99.71,63.15 99.62,63.06 99.62,62.92 99.71,62.83 100.8,62.83 100.9,62.74 100.9,62.61 100.8,62.51 99.71,62.51 99.62,62.42 99.62,62.29 99.71,62.2 100.8,62.2 100.9,62.1 100.9,61.97 100.8,61.88 99.71,61.88 99.62,61.79 99.62,61.65 99.71,61.56 100.8,61.56 100.9,61.47 100.9,61.34 100.8,61.24 99.71,61.24 99.62,61.15 99.62,61.02 99.71,60.93 100.8,60.93 100.9,60.83 100.9,60.5 98.37,57.98 98.37,56.48 98.28,56.39 98.01,56.39 97.92,56.3 97.92,56.17 98.01,56.07 98.28,56.07 98.37,55.98 98.37,55.37 98.3,55.3 97.03,55.3 96.94,55.2 96.94,55.07 97.03,54.98 98.1,54.98 98.2,54.89 98.2,54.76 98.1,54.66 97.03,54.66 96.94,54.57 96.94,54.44 97.03,54.35 98.1,54.35 98.2,54.25 98.2,54.12 98.1,54.03 97.03,54.03 96.94,53.93 96.94,53.8 97.03,53.71 98.1,53.71 98.2,53.62 98.2,53.49 98.1,53.39 97.03,53.39 96.94,53.3 96.94,53.17 97.03,53.08 98.1,53.08 98.2,52.98 98.2,52.85 98.1,52.76 97.03,52.76 96.94,52.66 96.94,52.53 97.03,52.44 98.1,52.44 98.2,52.35 98.2,51.93 97.97,51.7 97.84,51.7 97.55,51.99 97.42,51.99 97.33,51.9 97.33,51.77 97.62,51.48 97.62,51.35 97.52,51.25 97.39,51.25 97.1,51.54 96.97,51.54 96.88,51.45 96.88,51.32 97.17,51.03 97.17,50.9 96.84,50.57 v1(96.84,49.67)
ENETSW_SPI_MISO: length 37.8
  TOP w0.191: U12.6 101.33,47.16 101.47,47.31 101.98,47.31 v1(102.2,47.09)
  TOP w0.229: R75.1 TPAD13.1
  TOP w0.406: R202.2 v1(102.2,47.09) ; TPAD13.1 v1(122.44,69.56)
  L3_INT_1 w0.191: v1(122.44,69.56) 122.44,63.44 106.09,47.09 v1(102.2,47.09)
ENETSW_SPI_MOSI: length 28.6
  TOP w0.203: U3.7 101.18,55.71 R142.2
  TOP w0.406: v1(99.91,56.65) TPAD33.1 R142.2 ; R108.1 v1(121.15,63.71)
  L3_INT_1 w0.191: v1(99.91,56.65) 111.67,56.65 112.71,57.69 115.13,57.69 v1(121.15,63.71)
ENETSW_SPI_SC: length 33.3
  TOP w0.203: U12.7 100.93,47.2 100.8,47.33 R201.2
  TOP w0.406: R94.1 v1(121.15,65.75) ; R201.2 TPAD37.1 v1(104.61,49.36)
  L3_INT_1 w0.191: v1(104.61,49.36) 107.92,49.36 121.94,63.38 121.94,64.95 v1(121.15,65.75)
ENETSW_SPI_SCK: length 26.5
  TOP w0.203: R144.2 102.83,54.93 102.36,54.46 U3.6
  TOP w0.406: v1(105.45,55.84) TPAD34.1 R144.2 ; R98.1 v1(121.15,64.73)
  L3_INT_1 w0.191: v1(121.15,64.73) 121.62,64.25 121.62,63.52 113.94,55.84 v1(105.45,55.84)
EXP: length 47.1
  L3_INT_1 w0.191: v1(38.57,48.73) 37.59,47.75 37.59,45.54 38.56,44.57 38.56,42.32 38.46,42.22 38.46,39.94 v1(39.84,38.57)
  L6_INT_2 w0.191: v1(39.84,38.57) 40.7,37.7 40.7,37.51 42.26,35.96 43.4,35.96 44.33,36.88 51.3,36.88 v1(51.78,36.41) 53.77,38.4 60.46,38.4 v1(63.33,35.52)
  BOTTOM w0.406: v1(38.57,48.73) 39.36,48.73 40.04,48.04 41.19,48.04 43.12,46.11 43.47,46.11 v1(45.05,44.54)
HYPFLASH/QSPI_A_CS: length 4
  BOTTOM w0.279: R575.2 35.53,40.05 35.78,39.81 R581.2
  BOTTOM w0.406: U508.1 R581.2
HYPFLASH/QSPI_A_IO0: length 2.1
  BOTTOM w0.406: U508.5 R595.2
HYPFLASH/QSPI_A_IO1: length 2
  BOTTOM w0.406: U508.2 R585.2
HYPFLASH/QSPI_A_IO2: length 2
  BOTTOM w0.406: U508.3 R590.2
HYPFLASH/QSPI_A_IO3: length 2.1
  BOTTOM w0.406: U508.7 R586.2
HYPFLASH/QSPI_A_SCK: length 2.1
  BOTTOM w0.406: U508.6 R591.2
LED_BLUE: length 26.9
  TOP w0.406: R222.2 86.32,43.04 v1(86.91,43.62)
  L3_INT_1 w0.191: v1(86.91,43.62) 86.91,47.99 87.04,48.12 87.04,51.49 83.99,54.54
  L3_INT_1 w0.203: 83.99,54.54 83.99,55.04 v1(83.31,55.72)
  L6_INT_2 w0.203: v1(74.28,57.74) 75.96,59.42 78.45,59.42 82.15,55.72 v1(83.31,55.72)
  BOTTOM w0.203: R529.2 v1(74.28,57.74)
LED_GREEN: length 31.2
  TOP w0.406: R245.2 84.82,38.34 v1(84.82,37.53)
  L3_INT_1 w0.191: 83.93,51.84 84.25,51.53 84.25,43.49 84.82,42.91 v1(84.82,37.53)
  L3_INT_1 w0.203: 83.93,51.84 83.06,52.72 82.51,52.72 80.61,54.62 80.61,55.87 79.84,56.63 79.84,56.83 v1(77.74,58.94)
  L6_INT_2 w0.203: v1(74.28,56.73) 75.53,56.73 v1(77.74,58.94)
  BOTTOM w0.203: R533.2 v1(74.28,56.73)
LED_RED: length 31.3
  TOP w0.406: R255.2 v1(84.37,36.41)
  L3_INT_1 w0.191: v1(79.51,34.17) 79.92,34.58 79.92,37.26 81.28,38.62
  L3_INT_1 w0.203: v1(74.18,53.68) 77.03,50.84 77.88,50.84 79.69,49.02 79.69,42.33 81.28,40.73 81.28,38.62
  L6_INT_2 w0.191: v1(84.37,36.41) 84.01,36.05 82.41,36.05 81.47,35.11 80.45,35.11 v1(79.51,34.17)
  BOTTOM w0.203: R544.2 v1(74.18,53.68)
LEDRGB_BLUE: length 3.7
  TOP w0.406: D6.C3 94.56,40.41 94.5,40.47 TP43.1 R229.1 92.67,40.98
LEDRGB_GREEN: length 3.5
  TOP w0.406: D6.C2 TP46.1 R247.1 92.67,38.31
LEDRGB_RED: length 3.5
  TOP w0.406: D6.C1 94.56,36.21 94.5,36.15 TP48.1 R256.1 92.67,36.15
LIN1: length 26.7
  TOP w0.406: v1(10.76,45.63) TP29.1 R226.1 R225.1 ; R225.1 7.65,43.22 6.07,44.79 J13.1 ; R225.1 C58.1
  BOTTOM w0.406: R542.2 18.07,52.36 18.07,48.27 15.79,45.98 11.7,45.98 11.34,45.63 v1(10.76,45.63)
LIN1_OUT: length 39.8
  L6_INT_2 w0.191: J3.9 31.88,25.19 31.88,27.08 32.54,27.74 33.11,27.74 34.08,28.71 34.08,30.97 32.78,32.27 32.14,32.27 20,44.41 20,49.46 v1(16.24,53.22)
  BOTTOM w0.406: R543.2 v1(16.24,53.22)
LIN2: length 35.1
  TOP w0.406: R276.1 7.58,32.98 TP51.1 ; R276.1 R279.1 6.32,30.95 6.07,30.69 J17.1 ; R276.1 C77.1 8.9,34.68 8.98,34.76
  TOP w0.508: v1(7.91,34.76) 8.98,34.76
  L3_INT_1 w0.191: v1(7.91,34.76) 7.91,44.84 10.81,47.74 v1(10.81,55.61)
  BOTTOM w0.203: R535.2 11.16,55.61 v1(10.81,55.61)
LIN2_OUT: length 56.8
  L6_INT_2 w0.191: J3.15 34.91,20.94 27.76,20.94 26.8,21.9 26.8,31.02 26.96,31.17 26.96,32.85 16.95,42.85 16.95,49.05 16.67,49.33 16.27,49.33 16.26,49.31 11.09,54.48 11.09,54.54 10.33,55.29 10.33,55.81 10.6,56.08 v1(10.6,57.21)
  BOTTOM w0.203: R530.2 v1(10.6,57.21)
LVLRST_EN: length 1.2
  BOTTOM w0.203: U509.5 R610.2
MIC2005_CSLEW: length 1.9
  TOP w0.152: C103.2 U24.5
POWER_EN: length 12.6
  TOP w0.508: R300.1 v1(6.64,15.43)
  L6_INT_2 w0.508: v1(6.64,15.43) 11.98,15.43 14.03,13.37 v1(15.18,13.37)
  BOTTOM w0.279: v1(15.18,13.37) 15.54,13.74 15.86,13.74 16.24,14.12 U510.31
PTA0: length 65.7
  TOP w0.16: U7.115 v1(78.1,47.93) ; U8.140 82.84,46.43 83.15,46.73 v1(83.15,46.85)
  TOP w0.203: v1(83.15,46.85) 83.34,46.65 83.93,46.65
  TOP w0.406: v1(83.65,36.64) 83.24,36.22 83.24,34.59 84.19,33.64 89.29,33.64 90.51,32.42 95.26,32.42 97.7,29.98 97.7,28.66 97.69,28.65 97.69,28.34 97.18,27.84 97,27.84 96.99,27.85 95.98,27.85 95.26,27.13 95.26,26.12 95.28,26.11 95.28,23.16 103.64,14.79 v1(103.64,14.18) R302.2 ; R205.2 84.06,46.65 83.93,46.65
  BOTTOM w0.16: v1(78.1,47.93) 79.63,47.93 81.09,46.46 82.76,46.46 v1(83.15,46.85)
  BOTTOM w0.203: 83.93,46.65 83.83,46.65 83.63,46.85 v1(83.15,46.85)
  BOTTOM w0.406: 83.93,46.65 86.08,46.65 87.49,45.24 87.49,41.69 83.65,37.86 v1(83.65,36.64)
PTA0/ACMP0_IN0/ADC0_SE0: length 38.6
  TOP w0.406: v1(85.92,45.98) 85.92,46.19 85.51,46.59 R205.1
  BOTTOM w0.191: J4.15 62.35,25.52 66.44,25.52 67.11,26.19 67.11,27.2 67.97,28.06 68.98,28.06 70.88,29.95 70.88,30.97 74.42,34.5 78.16,34.5 85.33,41.68 85.33,45.4 v1(85.92,45.98)
PTA1: length 69
  TOP w0.16: v1(82.92,45.41) 82.46,45.41 82.44,45.42 U8.138 ; U7.113 v1(78.1,46.93)
  TOP w0.203: 83.93,45.41 v1(82.92,45.41)
  TOP w0.406: R274.2 v1(102.96,34.8) ; 83.93,45.41 84,45.41 R206.2
  L6_INT_2 w0.191: 84.46,46.27 84.46,47.53 85.62,48.69 v1(86.25,48.69)
  L6_INT_2 w0.203: 84.46,46.27 83.6,45.41 v1(82.92,45.41)
  BOTTOM w0.16: v1(82.92,45.41) 81.13,45.41 79.61,46.93 v1(78.1,46.93)
  BOTTOM w0.406: v1(102.96,34.8) 103.54,34.8 104.27,35.52 104.89,35.52 105.55,34.86 105.55,25.8 104.07,24.32 91.53,24.32 90.08,25.77 90.08,44.85 v1(86.25,48.69)
PTA1/ACMP0_IN1/ADC0_SE1: length 35.2
  TOP w0.406: v1(85.89,45.02) 85.48,45.43 R206.1
  BOTTOM w0.191: v1(85.89,45.02) 85.89,41.75 78.32,34.19 74.55,34.19 71.2,30.83 71.2,29.82 69.12,27.74 68.1,27.74 67.43,27.07 67.43,26.06 66.58,25.2 64.57,25.2 J4.18
PTA2/LPUART0_RX: length 157
  TOP w0.16: U7.105 v1(75.79,44.12) ; 76.3,40.98 v1(76.3,39.79)
  TOP w0.406: v1(63.99,73.61) 62.73,73.61 62.45,73.9 R40.1
  L3_INT_1 w0.191: v1(17.02,74.8) 18.09,73.73 18.74,73.73 20.55,71.92 20.55,70.41 23.82,67.15 23.82,63.74 23.18,63.1 21.55,63.1 19.84,61.4 19.84,60.33 19.46,59.94 17.54,59.94 16.78,59.19 16.78,57.69 17.54,56.93 v1(17.54,55.34)
  L6_INT_2 w0.191: 83.93,51.17 83.93,51.67 86.59,54.33 86.59,65.56 81.46,70.7 66.9,70.7 v1(63.99,73.61) 59.87,73.61 58.71,74.77 58.71,76.21 59.48,76.97 59.48,83.04 58.59,83.93 18.55,83.93 17.49,82.87 17.49,76.9 17.77,76.62 17.77,75.55 v1(17.02,74.8)
  L6_INT_2 w0.203: v1(75.79,44.12) 76.08,44.12 76.59,44.64 77.71,44.64 77.9,44.45 78.3,44.45 81.6,47.75 81.6,49.23 82.41,50.04 82.81,50.04 83.93,51.17
  BOTTOM w0.16: v1(75.79,44.12) 75.79,42.75 76.3,42.24 v1(76.3,39.79)
  BOTTOM w0.406: R536.1 v1(17.54,55.34)
PTA2/LPUART0_RX_LS: length 8.9
  TOP w0.203: 22.69,60.41 v1(22.69,61.18)
  TOP w0.406: v1(22.69,61.18) 22.69,61.68 TP10.1
  L3_INT_1 w0.203: v1(24.24,56.2) 22.71,57.73 22.71,60.66 22.69,60.68 v1(22.69,61.18)
  BOTTOM w0.203: v1(24.24,56.2) 23.98,56.46 23.47,56.46 23.32,56.32 U504.6
PTA3/LPUART0_TX: length 160.7
  TOP w0.16: U7.104 v1(75.29,44.59) ; 75.8,40.98 v1(75.8,39.32)
  TOP w0.406: R39.1 59.56,74.56 59.19,74.93 v1(59.19,75.04)
  L3_INT_1 w0.191: v1(17.17,75.83) 18.1,74.9 18.1,74.59 18.65,74.04 18.87,74.04 20.87,72.05 20.87,70.55 24.14,67.28 24.14,63.61 23.09,62.57 21.46,62.57 20.16,61.27 20.16,60.01 19.77,59.62 17.67,59.62 17.1,59.06 17.1,57.95 18.4,56.65 v1(18.4,55.28)
  L6_INT_2 w0.191: v1(17.17,75.83) 17.17,83 18.42,84.24 58.72,84.24 59.08,83.89 59.8,83.17 59.8,76.84 59.19,76.24 v1(59.19,75.04) 60.13,74.1 64.22,74.1 67.3,71.03 82.06,71.03 86.91,66.18 86.91,53.05 84.72,50.85 84.72,49.49 83.93,48.71
  L6_INT_2 w0.203: v1(75.29,44.59) 75.29,43.94 75.59,43.64 78.47,43.64 82.24,47.41 82.63,47.41 83.93,48.71
  BOTTOM w0.16: v1(75.29,44.59) 75.29,42.74 75.8,42.23 v1(75.8,39.32)
  BOTTOM w0.406: R540.1 18.81,54.87 v1(18.4,55.28)
PTA3/LPUART0_TX_LS: length 9.1
  TOP w0.203: v1(21.25,61.68) 21.25,60.84 R128.1
  L3_INT_1 w0.203: v1(23.62,55.91) 23.28,56.25 23.28,56.3 21.25,58.33 v1(21.25,61.68)
  BOTTOM w0.203: v1(23.62,55.91) 23.63,55.91 23.63,55.92 U504.7
PTA4/CMP0_OUT/JTAG_TMS/SWD_DIO: length 180.7
  TOP w0.16: U7.142 v1(76.97,61.43) ; U8.173 v1(82.91,62.94)
  TOP w0.406: v1(27.34,16.65) 27.33,16.63 R294.2
  L3_INT_1 w0.191: 83.93,62.94 93.33,62.94 95.82,65.42 95.82,66.35 95.81,66.35 95.81,70.74 v1(96.15,71.08)
  L3_INT_1 w0.203: 83.93,62.94 v1(82.91,62.94)
  L6_INT_2 w0.191: v1(96.15,71.08) 97.52,71.08 100.46,74.02 103.87,74.02 108.53,69.36 108.53,55.8 108.53,55.03 106.93,53.43 106.93,22.14 106.38,21.58 106.38,21.58 106.19,21.4 97.95,13.16 47.11,13.16 45.51,14.76 39.3,14.76 39.15,14.62 35.37,14.62 33.34,16.65 v1(27.34,16.65)
  BOTTOM w0.16: v1(82.91,62.94) 80.47,62.94 78.96,61.43 v1(76.97,61.43)
  BOTTOM w0.406: R507.2 95.59,70.52 v1(96.15,71.08)
PTA5/TCLK1_2/RESET: length 222.5
  TOP w0.16: U8.170 v1(82.44,61.44) ; U7.141 v1(78.1,60.93)
  TOP w0.406: R266.1 32.35,35.75 v1(31.94,36.15) ; TS6.1 97.75,63.54 97.47,63.26 v1(96.89,63.26) 96.2,62.57 R110.2 ; R289.2 v1(36.51,20.85) 37.24,20.85 37.96,20.13 42.28,20.13 J22.1 44.69,18.81 45.66,17.84 R295.2 ; R251.1 59.24,37.27 58.63,37.27 v1(58.48,37.12) ; D11.C v1(12.13,1.79)
  L3_INT_1 w0.191: 83.93,61.44 95.07,61.44 v1(96.89,63.26) ; v1(31.03,56.86) 30.69,56.52 30.52,56.52 27.91,53.91 27.91,48.46 29.69,46.69 29.69,46.04 31.94,43.79 v1(31.94,36.15) 31.94,32.24 29.03,29.33 29.03,21.54 29.55,21.02 35.87,21.02 36.04,20.85 v1(36.51,20.85)
  L3_INT_1 w0.203: 83.93,61.44 v1(82.44,61.44)
  L6_INT_2 w0.191: v1(35.47,56.68) 35.13,56.34 31.54,56.34 v1(31.03,56.86) ; v1(31.94,36.15) 40.86,36.15 41.84,35.17 46.11,35.17 46.62,35.68 48.64,35.68 48.72,35.6 51.83,35.6 54.31,38.08 54.85,38.08 56.19,36.73 58.1,36.73 v1(58.48,37.12) ; J22.1 42.82,19.59 22.33,19.59 10.99,8.24 10.99,2.93 v1(12.13,1.79)
  L6_INT_2 w0.203: v1(77.18,45.27) 77.66,45.27 77.84,45.45 78.3,45.45 78.87,46.02 78.87,54.48 77.15,56.2 74.13,56.2 73.75,56.58 73.75,58.96 75.72,60.93 v1(78.1,60.93)
  BOTTOM w0.16: v1(78.1,60.93) 79.09,60.93 79.6,61.44 v1(82.44,61.44)
  BOTTOM w0.191: v1(58.48,37.12) 59.67,37.12 60.04,37.49 60.43,37.49 60.82,37.09 62.62,37.09 62.92,36.8 65.07,36.8 65.54,37.27 77.64,37.27 79.86,39.49 79.86,42.47 77.51,44.81 77.51,44.94 v1(77.18,45.27)
  BOTTOM w0.203: R537.1 v1(35.47,56.68)
PTA6/FTM0_FLT1: length 115.2
  TOP w0.16: 65.29,40.98 v1(65.29,39.32) ; U7.85 v1(65.79,44.12)
  TOP w0.406: R282.1 v1(48.81,23.28)
  L3_INT_1 w0.191: 52.74,67.98 51.72,67.98 45.47,74.23 38.18,74.23 35.44,76.97 35.44,78.87 J2.8 ; v1(48.81,23.28) 49.14,22.94 69.34,22.94 71.86,25.46 71.86,34.97 v1(73.67,36.79)
  L3_INT_1 w0.203: v1(65.79,44.12) 64.6,42.93 58.79,42.93 57.44,44.29 57.44,64.8 55.51,66.73 53.99,66.73 52.74,67.98
  L6_INT_2 w0.191: v1(73.67,36.79) 70.83,36.79 69.18,38.44 66.17,38.44 65.99,38.62
  L6_INT_2 w0.203: v1(65.29,39.32) 65.99,38.62
  BOTTOM w0.16: v1(65.79,44.12) 65.79,40.64 65.29,40.14 v1(65.29,39.32)
PTA7/FTM0_FLT2: length 62
  TOP w0.16: U7.83 v1(64.79,44.12) ; 64.29,40.98 v1(64.29,39.32)
  L3_INT_1 w0.191: J2.5 40.19,78.86 40.19,77.3 42.91,74.58 45.56,74.58 51.81,68.34 52.74,68.34
  L3_INT_1 w0.203: 52.74,68.34 53.06,68.34 54.28,67.12 55.62,67.12 57.79,64.95 57.79,44.44 58.94,43.29 63.95,43.29 v1(64.79,44.12)
  BOTTOM w0.16: v1(64.29,39.32) 64.29,40.41 64.79,40.91 v1(64.79,44.12)
PTA8/LPUART2_RX: length 3.2
  TOP w0.203: R131.1 TP15.1
  TOP w0.406: TP15.1 v1(25.29,62.24)
  BOTTOM w0.203: U500.6 25.25,62.73 25.26,62.73 25.26,62.27 v1(25.29,62.24)
PTA8/LPUART2_RX/LPSPI2_SOUT/FXI: length 149.8
  TOP w0.16: U8.176 82.3,64.44 82.58,64.71 v1(82.58,65.28) ; U7.144 v1(77.63,62.43)
  L6_INT_2 w0.191: 52.74,64.97 52.1,64.97 51.39,65.68 47.49,65.68 45.64,63.82 42.52,63.82 42,64.34 30.16,64.34 26.23,68.26 v1(25.08,68.26) 25.08,65.03 22.24,62.19 21.02,62.19 18.83,60.01 16.65,60.01 15.33,58.69 13.27,58.69 13.08,58.51 12.53,57.95 12.53,54.89 16.82,50.6 17.2,50.6 19.2,48.59 19.2,43.76 31.55,31.41 31.55,23.25 31.76,23.04 v1(31.76,22.57)
  L6_INT_2 w0.203: 52.74,64.97 54.97,64.97 55.33,64.6 77.09,64.6 79.5,67.02 80.84,67.02 v1(82.58,65.28)
  BOTTOM w0.16: v1(77.63,62.43) 78.43,62.43 80.95,64.95 82.25,64.95 v1(82.58,65.28)
  BOTTOM w0.203: R512.1 25.41,67.93 v1(25.08,68.26)
  BOTTOM w0.406: J3.20 41.87,25.36 32.17,25.36 31.76,24.95 v1(31.76,22.57)
PTA9/LPUART2_TX: length 3.7
  TOP w0.203: v1(24.61,62.49) 24.27,62.49 TP12.1 23.58,61.22 23.71,61.1 R130.1
  BOTTOM w0.203: U500.7 24.85,62.73 v1(24.61,62.49)
PTA9/LPUART2_TX/LPSPI2_PCS0/FXI: length 150.4
  TOP w0.16: v1(83.83,64.83) 82.94,63.94 U8.175 ; U7.143 v1(78.1,61.93)
  L6_INT_2 w0.191: 52.74,65.34 52.73,65.32 52.6,65.32 52.56,65.28 52.23,65.28 51.52,65.99 47.39,65.99 46.4,66.98 45.27,66.98 43.32,65.03 30.36,65.03 26.34,69.05 24.73,69.05 v1(23.91,68.23) 23.91,66.34 21,63.42 16.69,63.42 16.09,62.82 16.09,59.9 15.2,59.01 13.14,59.01 12.76,58.64 12.76,58.64 12.21,58.08 12.21,57.82 12.21,57.82 12.21,54.76 16.69,50.28 17.06,50.28 18.88,48.46 18.88,42.48 28.79,32.57 v1(28.79,31.71)
  L6_INT_2 w0.203: v1(83.83,64.83) 81.29,67.37 79.35,67.37 76.94,64.96 55.49,64.96 55.11,65.34 52.74,65.34
  BOTTOM w0.16: v1(78.1,61.93) 78.7,61.93 81.24,64.48 83.48,64.48 v1(83.83,64.83)
  BOTTOM w0.203: v1(23.91,68.23) 24.19,67.96 R511.1
  BOTTOM w0.406: J3.23 44.48,27.84 30.02,27.84 29.2,28.65 29.2,31.3 v1(28.79,31.71)
PTA10/FTM1_CH4/FXIO_D0/JTAG_TDO: length 24.2
  TOP w0.203: v1(82.44,58.43) U8.164 80.25,58.43 80.25,58.43 U7.136
  L3_INT_1 w0.191: v1(93.73,65.94) 93.4,65.61 93.07,65.61 92.09,64.63 85.11,64.63 84.4,63.92 83.93,63.92
  L3_INT_1 w0.203: v1(82.44,58.43) 81.95,58.92 81.95,63.64 82.24,63.92 83.93,63.92
  BOTTOM w0.406: v1(93.73,65.94) 94.15,66.36 95.25,66.36 95.59,66.01 R515.2
PTA11/FTM1_CH5/FXIO_D1/CMP0_RRT: length 67
  TOP w0.16: U8.163 v1(82.91,57.93)
  TOP w0.203: U8.163 80.25,57.93 80.25,57.93 U7.135
  TOP w0.406: R324.1 78.7,21.8 J5.6
  L3_INT_1 w0.191: J5.6 79.81,25.52 84.24,25.52 84.89,26.17 84.89,26.77 86.18,28.06 86.78,28.06 87.46,28.73 87.46,29.85 88.65,31.04 88.65,44.35 88.65,44.35 88.65,53.51 84.77,57.39 83.93,57.39
  L3_INT_1 w0.203: v1(82.91,57.93) 83.39,57.93 83.93,57.39
PTA12/FTM1_CH6/CAN1_RX/LPI2C1_S: length 60.9
  TOP w0.16: U8.162 v1(82.44,57.43)
  TOP w0.203: U7.134 80.25,57.43 80.25,57.43 U8.162
  TOP w0.406: R325.1 81.24,21.8 J5.8
  L3_INT_1 w0.191: J5.8 82.49,27.87 84.06,27.87 84.89,28.71 84.89,29.42 88.33,32.86 88.33,44.21 88.33,44.22 88.33,53.38 84.79,56.91 83.93,56.91
  L3_INT_1 w0.203: v1(82.44,57.43) 83.28,57.43 83.8,56.91 83.93,56.91
PTA13/FTM1_CH7/FTM2_QD_PHA/SAI0: length 106.3
  TOP w0.16: U8.158 81.9,55.43 82.04,55.29 82.33,55.29 82.45,55.17 v1(82.45,54.71)
  TOP w0.203: U7.130 80.25,55.43 80.25,55.43 U8.158
  TOP w0.406: R326.1 v1(73.37,12.33)
  L3_INT_1 w0.191: 56.21,69.05 55.51,69.75 55.51,71.31 53.17,73.65 50.51,73.65 48.55,75.61 48.49,75.61 47,77.1 47,78.65 J1.23 ; 83.93,52.96 84.88,52.02 84.88,44.55 85.62,43.82 85.62,34.36 v1(81.98,30.72)
  L3_INT_1 w0.203: 56.21,69.05 56.36,68.9 56.39,68.9 61.04,64.25 77.91,64.25 80.35,61.81 80.35,56.8 v1(82.45,54.71) 82.45,54.23 82.94,53.73 83.17,53.73 83.93,52.96
  BOTTOM w0.406: v1(81.98,30.72) 80.81,30.72 79.95,29.86 79.95,18.91 v1(73.37,12.33)
PTA14/FTM0_FLT0/FTM3_FLT1/SAI0_: length 114.5
  TOP w0.203: v1(82.54,53.38) 82.54,53.73 82.33,53.93 U8.155 80.25,53.93 80.25,53.93 U7.127
  TOP w0.406: R329.1 v1(80.99,12.33)
  L3_INT_1 w0.191: 83.93,52.46 84.56,51.83 84.56,44.31 85.3,43.58 85.3,34.85 80.13,29.68 80.13,28.58 79.29,27.74 78.24,27.74 77.59,27.09 77.59,15.73 v1(80.99,12.33)
  L3_INT_1 w0.203: 83.93,52.46 83.02,53.38 v1(82.54,53.38)
  L6_INT_2 w0.191: J1.20 49.2,78.99 49.65,78.99 50.1,78.54 51.2,78.54 51.87,77.87 51.87,72.57 52.9,71.54 53.3,71.54 55.65,73.89 57.35,73.89 60.5,70.74 61.59,70.74 61.91,70.43 63.43,70.43 64.41,69.45 71.79,69.45
  L6_INT_2 w0.203: 71.79,69.45 72.16,69.45 72.73,68.87 81.54,68.87 85.63,64.78 85.63,55.33 83.68,53.38 v1(82.54,53.38)
PTA15: length 60.6
  TOP w0.203: 83.93,50.53 83.41,50.53 83.41,50.53 83.08,50.53 v1(82.84,50.76) 82.84,50.69 82.58,50.43 U8.148 80.25,50.43 80.25,50.43 U7.120
  TOP w0.406: R191.2 83.93,50.53 ; R304.2 v1(105.37,14.18)
  L3_INT_1 w0.191: v1(81.67,32.65) 82.54,33.52 82.54,36.29 84.03,37.77 84.03,37.86 84.09,37.91 84.09,40.92 81.96,43.05 81.96,49.88 v1(82.84,50.76)
  BOTTOM w0.406: v1(105.37,14.18) 103.52,16.04 96.46,16.04 87.57,24.93 87.57,30.19 85.1,32.65 v1(81.67,32.65)
PTA15/FTM1_CH2/ADC1_SE12: length 43.7
  TOP w0.406: R191.1 85.84,50.53 v1(85.92,50.45)
  BOTTOM w0.191: J4.21 67.11,25.2 68.67,25.2 71.83,28.37 71.83,30.57 74.81,33.55 79.57,33.55 80.32,34.3 84.16,34.3 88.23,38.37 88.23,45.58 85.45,48.36 85.45,49.99 v1(85.92,50.45)
PTA16: length 67.8
  TOP w0.16: U8.146 82.44,49.43 82.45,49.41 v1(82.46,49.41) ; U7.119 v1(78.1,49.93)
  TOP w0.203: v1(82.46,49.41) 83.07,49.41 83.1,49.44 83.5,49.44 83.51,49.44 83.93,49.44
  TOP w0.406: R275.2 v1(104.48,34.77) ; R193.2 83.93,49.44
  L6_INT_2 w0.191: v1(82.46,49.41) 83.08,49.41 83.11,49.44 83.56,49.44 84.32,50.19 84.32,51.13 v1(86.44,53.25)
  BOTTOM w0.16: v1(82.46,49.41) 81.94,49.93 v1(78.1,49.93)
  BOTTOM w0.406: v1(86.44,53.25) 86.44,51.53 92.72,45.25 92.72,25.77 93.64,24.85 103.85,24.85 105.02,26.02 105.02,33.54 104.48,34.07 v1(104.48,34.77)
PTA16/FTM1_CH3/ADC1_SE13: length 41.4
  TOP w0.406: R193.1 v1(85.98,49.44)
  BOTTOM w0.191: v1(85.98,49.44) 85.77,49.23 85.77,48.49 88.55,45.71 88.55,36.91 85.59,33.94 80.41,33.94 79.7,33.23 74.94,33.23 72.15,30.44 72.15,27.7 J4.24
PTA17/FTM0_CH6/ENET_RESET: length 52.5
  TOP w0.16: 68.79,40.98 v1(68.79,39.79) ; U7.92 v1(69.29,44.59)
  TOP w0.406: R261.1 58.41,36.15 v1(58.46,36.21) ; R267.1 34.93,34.92 v1(35.52,35.52)
  L3_INT_1 w0.191: v1(69.56,36.23) 68.79,37 68.79,38.62
  L3_INT_1 w0.203: 68.79,38.62 v1(68.79,39.79)
  L6_INT_2 w0.191: v1(35.52,35.52) 36.59,35.52 37.74,34.37 41.15,34.37 41.2,34.42 46.67,34.42 47.19,33.9 48.75,33.9 49.38,34.54 52.75,34.54 53.38,35.16 55.16,35.16 55.78,35.78 58.03,35.78 v1(58.46,36.21) 59.74,37.49 60.43,37.49 61.2,36.72 61.2,36.53 63.01,34.73 64.81,34.73 66.34,36.25 66.73,36.25 66.75,36.23 v1(69.56,36.23)
  BOTTOM w0.16: v1(68.79,39.79) 69.29,40.29 v1(69.29,44.59)
PTA18/FTM4_CH0/LPUART1_TX/LPSPI: length 14.8
  TOP w0.16: U8.1 v1(79.3,68.04)
  L3_INT_1 w0.191: 79.79,69.05 82.33,71.58 82.33,75.51 v1(81.8,76.03)
  L3_INT_1 w0.203: v1(79.3,68.04) 79.3,68.55 79.79,69.05
  L6_INT_2 w0.191: J6.16 79.78,76.36 80.46,76.36 80.78,76.03 v1(81.8,76.03)
